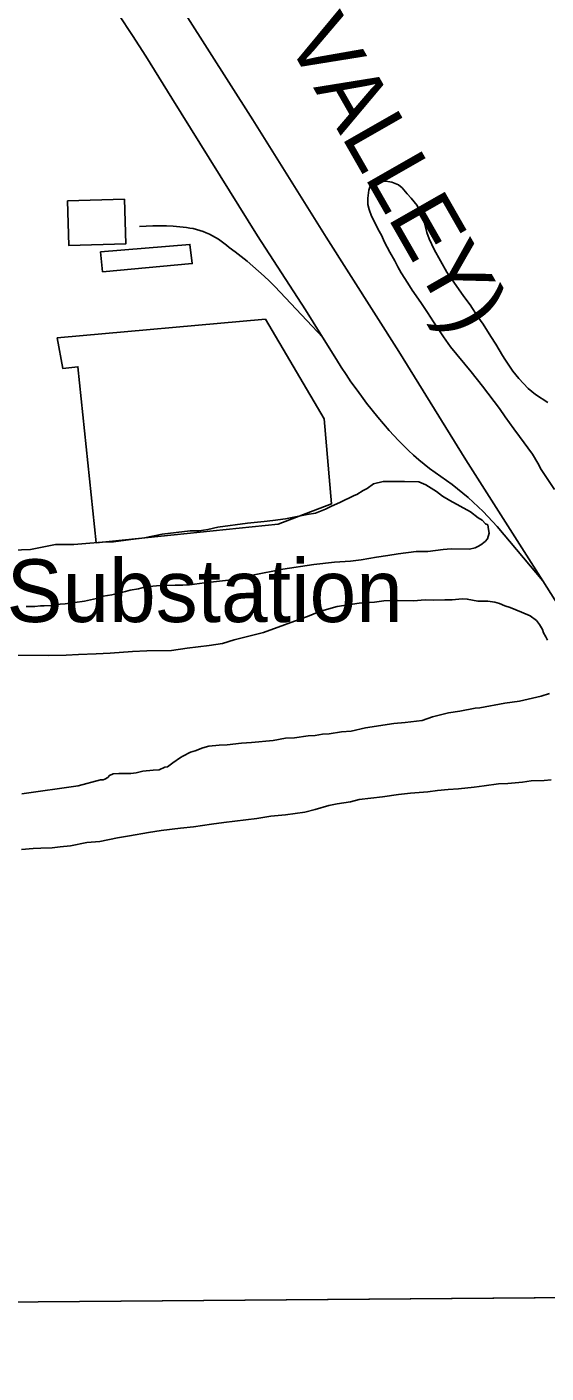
# Model space of a CAD drawing. Extents: x 3540316 to 3578335, y 553172 to 578787.
# Drawn here: x 3556756 to 3557443, y 558573 to 560356 of the extents above; entities that cross this region are included whole.
import ezdxf

# ---------------------------------------------------------------- set-up
doc = ezdxf.new("R2010")
doc.units = 0
for name, color, linetype in [('V-BLDG-OTLN', 7, 'Continuous'), ('V-GRID-FRAM', 7, 'Continuous'), ('V-RAIL-IDEN', 7, 'Continuous'), ('V-RAIL-TRAK', 7, 'Continuous'), ('V-SITE-OTLN', 7, 'Continuous'), ('V-SITE-OTLN-IDEN', 7, 'Continuous'), ('V-SITE-STRC', 7, 'Continuous'), ('V-SITE-VEGE', 7, 'Continuous')]:
    doc.layers.add(name, color=color, linetype=linetype)

msp = doc.modelspace()

# ---------------------------------------------------------------- linework, layer by layer
at = {"layer": 'V-BLDG-OTLN'}
msp.add_lwpolyline([(3556809.6, 560125.5), (3556884.7, 560127.6), (3556886.4, 560068.3), (3556811.3, 560066.2)], close=True, dxfattribs=at)
at = {"layer": 'V-GRID-FRAM'}
msp.add_lwpolyline([(3544387.2, 576756), (3576013, 576999.8), (3576161.1, 558817.2), (3544519.4, 558573.3), (3544387.2, 576756)], dxfattribs=at)
at = {"layer": 'V-RAIL-TRAK'}
msp.add_line((3557147.4, 559944.4), (3557090.9, 560004.7), dxfattribs=at)
for points in [[(3556728.8, 560749.3), (3556811.1, 560619.4), (3556887.9, 560495.8), (3556965.7, 560372.8), (3557054.6, 560232.5), (3557151.7, 560077.5), (3557247.8, 559925.9), (3557336.8, 559782.7), (3557438.3, 559622.3), (3557522.3, 559489.3), (3557616.4, 559339.2), (3557626.7, 559322.8), (3557718.1, 559176.8), (3557806.5, 559036.5), (3557894.5, 558897.7), (3557984.5, 558756), (3558033.3, 558677.5)], [(3557438.3, 559622.3), (3557378.2, 559694.2), (3557372.1, 559701), (3557365.9, 559707.6), (3557359.5, 559714.1), (3557353, 559720.4), (3557346.3, 559726.6), (3557339.5, 559732.6), (3557332.6, 559738.5), (3557325.5, 559744.2), (3557318.3, 559749.8), (3557310.9, 559755.2), (3557303.3, 559760.3), (3557295.9, 559765.6), (3557288.5, 559771.1), (3557281.3, 559776.8), (3557274.3, 559782.7), (3557267.4, 559788.7), (3557260.6, 559794.9), (3557254, 559801.3), (3557247.6, 559807.9), (3557241.3, 559814.6), (3557235.2, 559821.4), (3557227.5, 559830.3), (3557220, 559839.2), (3557212.6, 559848.3), (3557205.3, 559857.5), (3557198.3, 559866.8), (3557191.4, 559876.3), (3557184.6, 559885.9), (3557178.1, 559895.6), (3557171.7, 559905.4), (3557165.5, 559915.4), (3557144.9, 559948.3), (3557124.2, 559981.2), (3557103.3, 560013.9), (3557082.1, 560046.6), (3557060.8, 560079.1), (3556947.5, 560261.4), (3556930.3, 560289.2), (3556912.9, 560316.8), (3556895.2, 560344.3), (3556877.3, 560371.7)], [(3557090.9, 560004.7), (3557084, 560011.9), (3557076.9, 560019), (3557069.7, 560025.8), (3557062.3, 560032.5), (3557054.8, 560039.1), (3557047.2, 560045.5), (3557039.4, 560051.7), (3557031.4, 560057.7), (3557023.4, 560063.5), (3557020, 560066.6), (3557016.5, 560069.4), (3557012.9, 560072.2), (3557009.1, 560074.7), (3557005.3, 560077.1), (3557001.3, 560079.3), (3556997.2, 560081.3), (3556993.1, 560083.2), (3556988.9, 560084.8), (3556984.6, 560086.2), (3556980.2, 560087.5), (3556975.8, 560088.6), (3556971.3, 560089.4), (3556966.8, 560090.1), (3556958, 560091), (3556949.2, 560091.8), (3556940.3, 560092.2), (3556931.4, 560092.4), (3556922.5, 560092.3), (3556913.6, 560092), (3556904.8, 560091.4)]]:
    msp.add_lwpolyline(points, dxfattribs=at)
at = {"layer": 'V-SITE-OTLN'}
msp.add_lwpolyline([(3556795.8, 559943.9), (3557071.3, 559968.7), (3557148.9, 559836.9), (3557159, 559724.2), (3557088.3, 559697.1), (3556847.4, 559672.7), (3556823.1, 559905.8), (3556803, 559903.5)], close=True, dxfattribs=at)
at = {"layer": 'V-SITE-STRC'}
msp.add_lwpolyline([(3556852.9, 560058.1), (3556971.4, 560067.7), (3556974.4, 560042.3), (3556855.9, 560031.5)], close=True, dxfattribs=at)
at = {"layer": 'V-SITE-VEGE'}
for p, q in [((3557423, 559357.3), (3557440.1, 559357.8)), ((3557440.1, 559357.8), (3557449.4, 559358.9)), ((3557247.7, 559339.4), (3557263.3, 559341)), ((3557263.3, 559341), (3557286.1, 559343.1)), ((3557286.1, 559343.1), (3557299.1, 559344.7)), ((3557299.1, 559344.7), (3557313.1, 559346.2)), ((3557313.1, 559346.2), (3557327.1, 559346.8)), ((3557327.1, 559346.8), (3557347.8, 559348.9)), ((3557347.8, 559348.9), (3557360.8, 559351)), ((3557360.8, 559351), (3557380, 559353.6)), ((3557380, 559353.6), (3557392.4, 559354.1)), ((3557392.4, 559354.1), (3557411.6, 559355.7)), ((3557411.6, 559355.7), (3557423, 559357.3)), ((3557137.3, 559319.6), (3557155.4, 559324.8)), ((3557155.4, 559324.8), (3557166.3, 559326.9)), ((3557166.3, 559326.9), (3557184, 559329.5)), ((3557184, 559329.5), (3557195.4, 559332.6)), ((3557195.4, 559332.6), (3557226.5, 559336.3)), ((3557226.5, 559336.3), (3557247.7, 559339.4)), ((3557016.5, 559302.3), (3557060, 559307.6)), ((3557060, 559307.6), (3557078.7, 559310.7)), ((3557078.7, 559310.7), (3557097.9, 559312.3)), ((3557097.9, 559312.3), (3557123.3, 559315.9)), ((3557123.3, 559315.9), (3557137.3, 559319.6)), ((3556891.5, 559284.5), (3556916.4, 559289.2)), ((3556916.4, 559289.2), (3556933.5, 559291.8)), ((3556933.5, 559291.8), (3556958.9, 559295)), ((3556958.9, 559295), (3556976, 559296.6)), ((3556976, 559296.6), (3556999.9, 559300.2)), ((3556999.9, 559300.2), (3557016.5, 559302.3)), ((3556774.3, 559268.3), (3556788.9, 559268.8)), ((3556788.9, 559268.8), (3556799.8, 559269.9)), ((3556799.8, 559269.9), (3556813.2, 559271.5)), ((3556813.2, 559271.5), (3556835, 559275.6)), ((3556835, 559275.6), (3556852.1, 559277.2)), ((3556852.1, 559277.2), (3556875.5, 559281.9)), ((3556875.5, 559281.9), (3556891.5, 559284.5)), ((3556748.4, 559266.7), (3556764, 559267.8)), ((3556764, 559267.8), (3556774.3, 559268.3)), ((3557481.9, 558673.2), (3555894.7, 558661))]:
    msp.add_line(p, q, dxfattribs=at)
for points in [[(3557215, 560099.2), (3557211.7, 560105.2), (3557208.5, 560114.1), (3557206.9, 560120.7), (3557206.9, 560129), (3557208.1, 560139.5), (3557209.8, 560145), (3557213.7, 560150.5), (3557219.3, 560151.6), (3557230.9, 560151.5), (3557238.6, 560150.3), (3557247.4, 560146.4), (3557252.3, 560142.5), (3557258.9, 560134.7), (3557264.4, 560129.1), (3557272, 560119.1), (3557275.8, 560110.8), (3557281.8, 560096.4), (3557285, 560083.7), (3557288.2, 560074.9), (3557294.8, 560061), (3557311.6, 560031.1), (3557334, 559998.9), (3557342.2, 559987.8), (3557352.6, 559971.7), (3557359.7, 559962.3), (3557369.5, 559945.6), (3557376.1, 559935.6), (3557385.3, 559920.7), (3557388.1, 559915.7), (3557399, 559900.1), (3557406.6, 559890.2), (3557419.2, 559876.8), (3557428.6, 559869), (3557445.1, 559858.4)], [(3557454.1, 559743), (3557436.1, 559769.6), (3557431.8, 559777.9), (3557424.7, 559790.1), (3557407.7, 559813.4), (3557400.1, 559823.4), (3557388.6, 559839.5), (3557381, 559850.6), (3557358.5, 559880), (3557343.8, 559898.9), (3557316.4, 559932.2), (3557307.1, 559945.5), (3557294, 559965), (3557285.9, 559977.7), (3557277.1, 559991), (3557265.7, 560007.1), (3557259.7, 560016.6), (3557250.9, 560029.9), (3557246.6, 560038.2), (3557242.8, 560045.9), (3557236.2, 560057.6), (3557229.1, 560070.9), (3557224.8, 560079.8), (3557220.4, 560087.5), (3557215, 560099.2)], [(3556736.5, 559662.9), (3556760.3, 559663.8), (3556793.5, 559670.2), (3556817.7, 559670.6), (3556833.8, 559671.5), (3556855.3, 559673.6), (3556870.2, 559674), (3556893.4, 559677.2), (3556911.1, 559679.2), (3556934.9, 559684), (3556971.9, 559688.7), (3556983.5, 559688.6), (3556995.1, 559690.2), (3557008.4, 559693.4), (3557047.6, 559698.6), (3557069.7, 559700.7), (3557081.3, 559702.2), (3557097.9, 559704.3), (3557126.6, 559710.2), (3557137.7, 559711.8), (3557151, 559717.2), (3557158.7, 559721), (3557169.8, 559725.9), (3557188.6, 559735.1), (3557192.5, 559736.7), (3557200.8, 559741.7), (3557205.8, 559744.4), (3557214.2, 559750.9), (3557227.4, 559753.6), (3557240.7, 559754), (3557255.6, 559753.9), (3557274.3, 559753.2), (3557283.7, 559749.3), (3557294.1, 559742.6), (3557298, 559740.4), (3557305.7, 559734.2), (3557315.6, 559728.6), (3557343, 559713.5), (3557352.9, 559705.7), (3557358.4, 559702.4), (3557362.8, 559697.9), (3557365.6, 559696.3), (3557366.6, 559690.2), (3557367.7, 559685.2), (3557365.4, 559678), (3557362.1, 559674.2), (3557356.5, 559669.8), (3557352.6, 559667.6), (3557348.8, 559666), (3557341.6, 559664.4), (3557317.3, 559664.6), (3557306.8, 559663.6), (3557286.3, 559661), (3557270.9, 559661.1), (3557247.1, 559657.9), (3557233.3, 559655.8), (3557218.4, 559653.7), (3557197.9, 559650), (3557184.1, 559648.5), (3557162.6, 559647), (3557135.5, 559643.9), (3557094.6, 559637.6), (3557054.3, 559629.6), (3557029.9, 559624.2), (3557014.5, 559622.2), (3556990.7, 559619.6), (3556977.4, 559618), (3556962, 559616.5), (3556952, 559616.6), (3556939.9, 559616.1), (3556932.2, 559616.1), (3556922.2, 559615.1), (3556915.6, 559614.6), (3556909.5, 559613.6), (3556903.4, 559611.9), (3556892.4, 559609.8), (3556886.3, 559608.2), (3556875.2, 559605.5), (3556868, 559603.9), (3556856.4, 559601.8), (3556847.6, 559599.1), (3556832.1, 559595.4), (3556806.1, 559591.7), (3556799.5, 559591.2), (3556790.6, 559590.2), (3556787.9, 559589.6), (3556778.5, 559589.1), (3556773.5, 559589.2), (3556766.3, 559588.1), (3556754.7, 559588.2)], [(3556730.2, 559523.8), (3556784.8, 559523.4), (3556807.5, 559523.8), (3556824, 559524.8), (3556847.2, 559525.7), (3556866, 559526.7), (3556895.3, 559528.7), (3556914.6, 559529.6), (3556947.2, 559529.9), (3556967.6, 559533.1), (3556996.9, 559536.8), (3557014.6, 559539.4), (3557030.1, 559544.2), (3557068.8, 559553.9), (3557129.1, 559576.1), (3557143, 559581.5), (3557166.2, 559588.5), (3557195.5, 559592.7), (3557215.9, 559594.2), (3557228.1, 559595.7), (3557246.3, 559596.2), (3557267.3, 559596), (3557282.8, 559597), (3557293.8, 559596.9), (3557308.7, 559597.3), (3557318.6, 559597.3), (3557331.9, 559598.3), (3557338.5, 559598.2), (3557352.3, 559595.4), (3557365.6, 559595.3)], [(3557365.6, 559595.3), (3557374.9, 559594.1), (3557381, 559592.4), (3557388.1, 559589), (3557395.3, 559586.8), (3557410.2, 559580.6), (3557421.7, 559576.1), (3557430, 559569.9), (3557434.3, 559564.4), (3557438.1, 559557.7), (3557439.2, 559553.3), (3557442.5, 559548.3), (3557444.7, 559543.9)], [(3557447.4, 559473.2), (3557436.4, 559469.4), (3557407.6, 559463), (3557388.3, 559460.4), (3557355.1, 559454), (3557349, 559453.5), (3557328.6, 559449.8), (3557313.7, 559447.7), (3557292.6, 559442.3), (3557278.8, 559437.5), (3557256.2, 559434.9), (3557241.2, 559433.3), (3557203.7, 559427.6), (3557184.9, 559423.3), (3557172.1, 559422.3), (3557155.6, 559419.6), (3557146.7, 559419.1), (3557137.3, 559417.6), (3557127.9, 559417.1), (3557109.7, 559414.5), (3557098.1, 559414), (3557081.5, 559410.8), (3557052.8, 559408.3), (3557039.6, 559407.3), (3557020.8, 559405.2), (3557010.3, 559404.7), (3556996.5, 559403.2), (3556988.7, 559401), (3556978.2, 559397.2), (3556972.1, 559395.6), (3556962.1, 559390.2), (3556958.8, 559388.5), (3556948.8, 559381.4), (3556947.2, 559379.8), (3556941.6, 559376), (3556938.3, 559375.4), (3556930.5, 559372.2), (3556922.8, 559371.7), (3556909, 559370.1), (3556900.1, 559368), (3556893, 559367), (3556877.5, 559367.1), (3556869.8, 559366.6), (3556864.8, 559364.4), (3556862.6, 559361.7), (3556858.7, 559359.5), (3556856.5, 559358.9), (3556853.2, 559359), (3556823.5, 559350.8), (3556749.1, 559340.3)]]:
    msp.add_lwpolyline(points, dxfattribs=at)

# ---------------------------------------------------------------- texts
at = {"layer": 'V-RAIL-IDEN'}
msp.add_text('VALLEY)', height=83, rotation=299.7448, dxfattribs=at).set_placement((3557097.5, 560339.8))
at = {"layer": 'V-SITE-OTLN-IDEN'}
msp.add_text('Substation', height=83, dxfattribs=at).set_placement((3556728.7, 559567.7))

doc.saveas('drawing.dxf')
